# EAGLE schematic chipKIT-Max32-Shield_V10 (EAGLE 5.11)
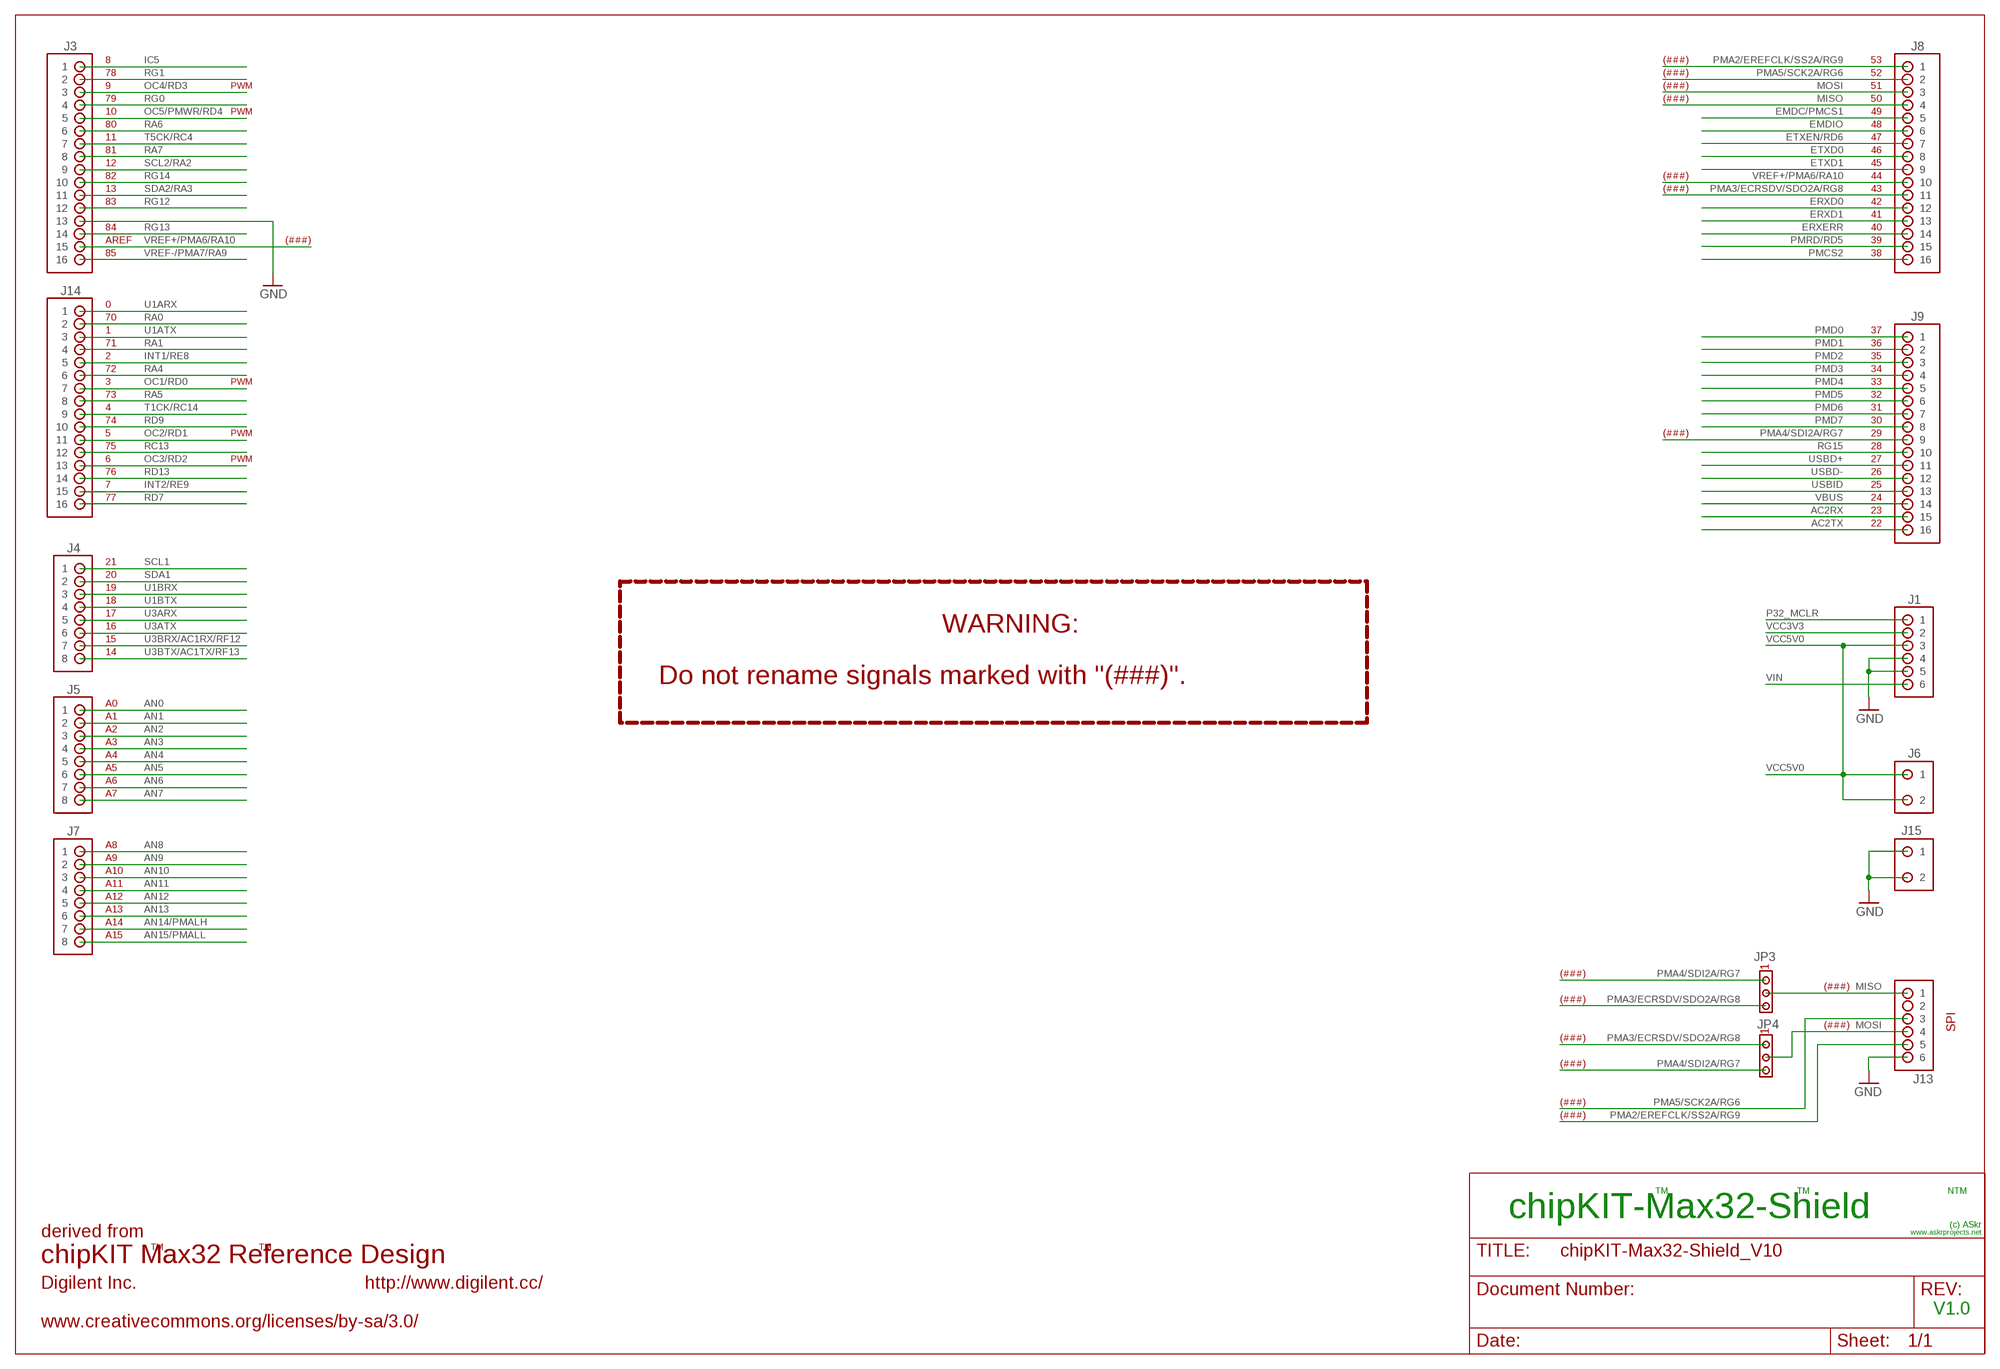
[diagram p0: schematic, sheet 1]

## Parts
J1  HDR-1X6  [HDR-1X6]
J3  HDR-2X8  [HDR-2X8]
J4  HDR-1X8  [HDR-1X8]
J5  HDR-1X8  [HDR-1X8]
J6  HDR-1X2  [HDR-1X2]
J7  HDR-1X8  [HDR-1X8]
J8  HDR-2X8  [HDR-2X8]
J9  HDR-2X8  [HDR-2X8]
J13  HDR-2X3  [HDR-2X3]
J14  HDR-2X8  [HDR-2X8]
J15  HDR-1X2  [HDR-1X2]
JP3  JPR-1X3  [JPR-1X3]
JP4  JPR-1X3  [JPR-1X3]

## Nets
AC2RX: J9.15
AC2TX: J9.16
AN0: J5.1
AN1: J5.2
AN2: J5.3
AN3: J5.4
AN4: J5.5
AN5: J5.6
AN6: J5.7
AN7: J5.8
AN8: J7.1
AN9: J7.2
AN10: J7.3
AN11: J7.4
AN12: J7.5
AN13: J7.6
AN14/PMALH: J7.7
AN15/PMALL: J7.8
EMDC/PMCS1: J8.5
EMDIO: J8.6
ERXD0: J8.12
ERXD1: J8.13
ERXERR: J8.14
ETXD0: J8.8
ETXD1: J8.9
ETXEN/RD6: J8.7
GND: J1.4 J1.5 J3.13 J13.6 J15.1 J15.2
IC5: J3.1
INT1/RE8: J14.5
INT2/RE9: J14.15
MISO: J8.4 J13.1 JP3.2
MOSI: J8.3 J13.4 JP4.2
OC1/RD0: J14.7
OC2/RD1: J14.11
OC3/RD2: J14.13
OC4/RD3: J3.3
OC5/PMWR/RD4: J3.5
P32_MCLR: J1.1
PMA2/EREFCLK/SS2A/RG9: J8.1 J13.5
PMA3/ECRSDV/SDO2A/RG8: J8.11 JP3.3 JP4.1
PMA4/SDI2A/RG7: J9.9 JP3.1 JP4.3
PMA5/SCK2A/RG6: J8.2 J13.3
PMCS2: J8.16
PMD0: J9.1
PMD1: J9.2
PMD2: J9.3
PMD3: J9.4
PMD4: J9.5
PMD5: J9.6
PMD6: J9.7
PMD7: J9.8
PMRD/RD5: J8.15
RA0: J14.2
RA1: J14.4
RA4: J14.6
RA5: J14.8
RA6: J3.6
RA7: J3.8
RC13: J14.12
RD7: J14.16
RD9: J14.10
RD13: J14.14
RG0: J3.4
RG1: J3.2
RG12: J3.12
RG13: J3.14
RG14: J3.10
RG15: J9.10
SCL1: J4.1
SCL2/RA2: J3.9
SDA1: J4.2
SDA2/RA3: J3.11
T1CK/RC14: J14.9
T5CK/RC4: J3.7
U1ARX: J14.1
U1ATX: J14.3
U1BRX: J4.3
U1BTX: J4.4
U3ARX: J4.5
U3ATX: J4.6
U3BRX/AC1RX/RF12: J4.7
U3BTX/AC1TX/RF13: J4.8
USBD+: J9.11
USBD-: J9.12
USBID: J9.13
VBUS: J9.14
VCC3V3: J1.2
VCC5V0: J1.3 J6.1 J6.2
VIN: J1.6
VREF+/PMA6/RA10: J3.15 J8.10
VREF-/PMA7/RA9: J3.16
Unconnected: J13.2

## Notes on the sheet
- 8 | (###) | 53
- 78 | (###) | 52
- 9 | PWM | (###) | 51
- 79 | (###) | 50
- 10 | PWM | 49
- 80 | 48
- 11 | 47
- 81 | 46
- 12 | 45
- 82 | (###) | 44
- 13 | (###) | 43
- 83 | 42
- 41
- 84 | 40
- AREF | (###) | 39
- 85 | 38
- 0
- 70
- 1 | 37
- 71 | 36
- 2 | 35
- 72 | 34
- 3 | PWM | 33
- 73 | 32
- 4 | 31
- 74 | 30
- 5 | PWM | (###) | 29
- 75 | 28
- 6 | PWM | 27
- 76 | 26
- 7 | 25
- 77 | 24
- 23
- 22
- 21
- 20
- 19
- 18
- 17
- 16
- WARNING:
- 15
- 14
- Do not rename signals marked with "(###)".
- A0
- A1
- A2
- A3
- A4
- A5
- A6
- A7
- A8
- A9
- A10
- A11
- A12
- A13
- A14
- A15
- (###)
- (###)
- (###)
- (###)
- SPI
- (###)
- (###)
- (###)
- (###)
- TM | TM | NTM
- chipKIT-Max32-Shield
- (c) ASkr
- www.askrprojects.net
- derived from
- TM | TM
- chipKIT Max32 Reference Design
- http://www.digilent.cc/
- Digilent Inc.
- V1.0
- www.creativecommons.org/licenses/by-sa/3.0/

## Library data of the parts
J1 = Mechanical:HDR-1X6
J3 J8 J9 J14 = Mechanical:HDR-2X8: 100mil 2x8 header
J4 J5 J7 = Mechanical:HDR-1X8
J6 J15 = Mechanical:HDR-1X2
J13 = Mechanical:HDR-2X3
JP3 JP4 = Mechanical:JPR-1X3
